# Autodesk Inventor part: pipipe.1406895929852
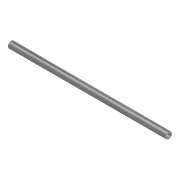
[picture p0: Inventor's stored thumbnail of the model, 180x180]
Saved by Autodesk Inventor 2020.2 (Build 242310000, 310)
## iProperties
Manager: www.cadconsulting.pl
Company: Fabian Stasiak CAD Consulting
IsCustomPart: 1
NAME: PIPING: JIS G 3458 Pipe
DATA: <meta><inlinegroups number="1" deflen="10"></inlinegroups><connections number="2"></connections><angles><a>3.14159265358979</a></angles></meta>
Created: 2014-08
Material: Stal, stopowa
Description: Rura
Document SubType Name: Modeling
Standard: JIS G 3458
Designer: F.Stasiak
Standards Organization: JIS
Language: pl-PL
Size Designation: 40 A x Sch 80 - 100
Categories: <MemberInstance><Categories><Category DisplayName="Rury cienko- i grubościenne" InternalName="4347fa0f-2144-441d-94cd-e3e15c92b736" Mnemonic="TUBEANDPIPE"><Cate
Stock Number: JIS G 3458 Rura 40 A x Sch 80
Density: 7.73 g/cm^3
Appearance: Częściowo polerowana
Catalog Web Link: www.expertbooks.pl
L: 1186,000 mm
PL: 1186,000 mm
Author: F.Stasiak
Subject: Zbiór ćwiczeń. Autodesk Inventor 2020. Kurs Professional
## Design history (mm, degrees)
sketch "Sketch1"
  geometry: C1 r 24.3 at (0, 0); C2 r 19.2 at (0, 0); 1 further point
  constraints: 2 centre point, 2 coincident, 1 concentric
  dimensions: "d0" = 48.6 diameter of C1 (= OD); "d1" = 38.4 diameter of C2 (= OD - 2 x t)
extrude "Extrusion1" new body sketch "Sketch1" distance "d2" = 1186 (= L); taper "d3" = 0 deg
workaxis "Work Axis1"
workpoint "Work Point1"
workaxis "Work Axis2"
workpoint "Work Point2"
body "Solid1"
other parameters: "OD" = 48.6 [user parameter; used in 2 equation terms], "t" = 5.1 [user parameter; used in 1 equation term], "L" = 1186 (= PL) [user parameter; used in 1 equation term], "ID" = 38.4 [user parameter], "PL" = 1186 [user parameter; used in 1 equation term], "Size_Designation" = 12.345 [user parameter]
